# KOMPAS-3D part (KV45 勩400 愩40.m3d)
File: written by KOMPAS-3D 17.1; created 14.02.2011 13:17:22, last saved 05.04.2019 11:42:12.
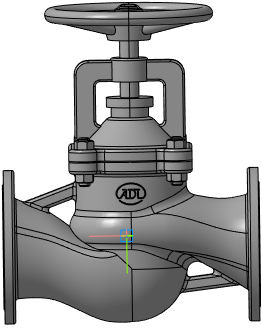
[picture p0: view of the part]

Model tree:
1. Плоскость XY
2. Плоскость ZX
3. Плоскость ZY
4. Ось X
5. Ось Y
6. Ось Z
7. Начало координат
8. Операция без истории:2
